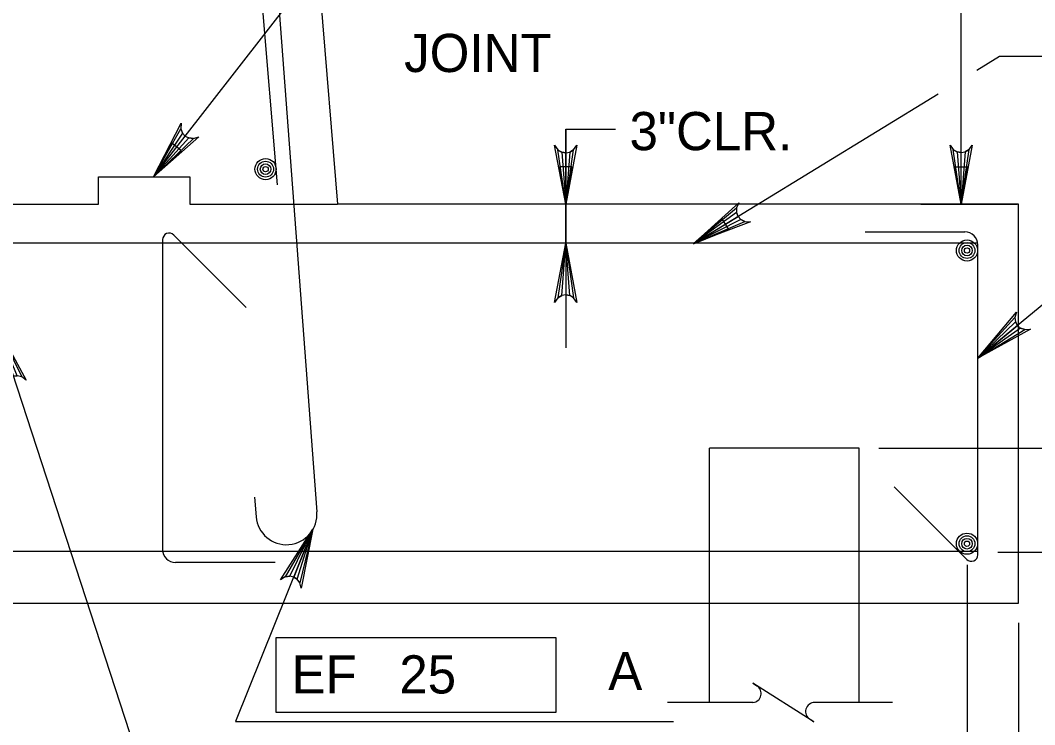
# Model space of a CAD drawing. Extents: x 638340 to 640242, y 295465 to 298435.
# Drawn here: x 639971.8 to 640051.5, y 298208.5 to 298263.9 of the extents above; entities that cross this region are included whole.
import ezdxf

# ---------------------------------------------------------------- set-up
doc = ezdxf.new("R2010")
doc.units = 0
for name, color, linetype in [('Level 3', 7, 'Continuous'), ('Level 4', 7, 'Continuous'), ('Level 5', 7, 'Continuous'), ('Level 6', 7, 'Continuous'), ('Level 7', 7, 'Continuous'), ('Level 8', 7, 'Continuous'), ('Level 9', 7, 'Continuous')]:
    doc.layers.add(name, color=color, linetype=linetype)

msp = doc.modelspace()

# ---------------------------------------------------------------- linework, layer by layer
at = {"layer": 'Level 3'}
for p, q in [((640039.268, 298230.284), (640095.226, 298230.284)), ((640048.611, 298222.099), (640081.55, 298222.099))]:
    msp.add_line(p, q, dxfattribs=at)
at = {"layer": 'Level 4'}
for p, q in [((640045.737, 298249.445), (640045.737, 298311.252)), ((639982.254, 298251.603), (639997.895, 298271.717)), ((640046.971, 298259.984), (640048.764, 298261.081)), ((640048.764, 298261.081), (640084.556, 298261.081)), ((640024.752, 298246.374), (640043.921, 298258.115)), ((640024.752, 298246.374), (640043.921, 298258.115)), ((640014.652, 298255.332), (640014.652, 298238.165)), ((640014.653, 298246.374), (640014.653, 298255.332)), ((640014.653, 298255.332), (640018.566, 298255.332)), ((640042.568, 298249.445), (640050.156, 298249.445)), ((640042.568, 298249.445), (640050.156, 298249.445)), ((640053.121, 298242.35), (640047.051, 298237.338)), ((639969.961, 298239.776), (639984.381, 298195.585)), ((639994.782, 298223.906), (639988.69, 298208.795)), ((640046.201, 298221.101), (640046.201, 298175.428)), ((640050.258, 298216.56), (640050.258, 298158.658)), ((639991.877, 298215.41), (640013.875, 298215.41)), ((639991.877, 298209.515), (639991.877, 298215.41)), ((640013.875, 298215.41), (640013.875, 298209.515)), ((640013.875, 298209.515), (639991.877, 298209.515)), ((639988.69, 298208.795), (640023.134, 298208.795))]:
    msp.add_line(p, q, dxfattribs=at)
for points in [[(639982.254, 298251.603), (639984.421, 298255.81), (639984.398, 298255.375), (639984.529, 298255.038), (639984.743, 298254.803), (639985.022, 298254.656), (639985.381, 298254.61), (639985.797, 298254.739), (639982.254, 298251.603), (639985.381, 298254.61), (639985.022, 298254.656), (639982.254, 298251.603), (639984.743, 298254.803), (639984.529, 298255.038), (639982.254, 298251.603), (639984.398, 298255.375)], [(640014.653, 298249.437), (640013.781, 298254.088), (640014.029, 298253.73), (640014.341, 298253.545), (640014.653, 298253.491), (640014.964, 298253.545), (640015.276, 298253.73), (640015.524, 298254.088), (640014.653, 298249.437), (640015.276, 298253.73), (640014.964, 298253.545), (640014.653, 298249.437), (640014.653, 298253.491), (640014.341, 298253.545), (640014.653, 298249.437), (640014.029, 298253.73)], [(640045.737, 298249.445), (640044.866, 298254.096), (640045.113, 298253.739), (640045.425, 298253.554), (640045.737, 298253.5), (640046.049, 298253.554), (640046.361, 298253.739), (640046.608, 298254.096), (640045.737, 298249.445), (640046.361, 298253.739), (640046.049, 298253.554), (640045.737, 298249.445), (640045.737, 298253.5), (640045.425, 298253.554), (640045.737, 298249.445), (640045.113, 298253.739)], [(640024.752, 298246.374), (640028.264, 298249.547), (640028.087, 298249.148), (640028.092, 298248.786), (640028.21, 298248.49), (640028.418, 298248.253), (640028.738, 298248.085), (640029.175, 298248.06), (640024.752, 298246.374), (640028.738, 298248.085), (640028.418, 298248.253), (640024.752, 298246.374), (640028.21, 298248.49), (640028.092, 298248.786), (640024.752, 298246.374), (640028.087, 298249.148)], [(640024.752, 298246.374), (640028.264, 298249.547), (640028.087, 298249.148), (640028.092, 298248.786), (640028.21, 298248.49), (640028.418, 298248.253), (640028.738, 298248.085), (640029.175, 298248.06), (640024.752, 298246.374), (640028.738, 298248.085), (640028.418, 298248.253), (640024.752, 298246.374), (640028.21, 298248.49), (640028.092, 298248.786), (640024.752, 298246.374), (640028.087, 298249.148)], [(640014.653, 298246.374), (640015.524, 298241.722), (640015.276, 298242.08), (640014.964, 298242.265), (640014.653, 298242.319), (640014.341, 298242.265), (640014.029, 298242.08), (640013.781, 298241.722), (640014.653, 298246.374), (640014.029, 298242.08), (640014.341, 298242.265), (640014.653, 298246.374), (640014.653, 298242.319), (640014.964, 298242.265), (640014.653, 298246.374), (640015.276, 298242.08)], [(640047.051, 298237.339), (640050.083, 298240.971), (640049.964, 298240.553), (640050.02, 298240.194), (640050.179, 298239.919), (640050.418, 298239.713), (640050.759, 298239.591), (640051.193, 298239.628), (640047.051, 298237.339), (640050.759, 298239.591), (640050.418, 298239.713), (640047.051, 298237.339), (640050.179, 298239.919), (640050.02, 298240.194), (640047.051, 298237.339), (640049.964, 298240.553)], [(639969.961, 298239.776), (639972.234, 298235.625), (639971.886, 298235.887), (639971.533, 298235.966), (639971.219, 298235.921), (639970.938, 298235.773), (639970.699, 298235.501), (639970.574, 298235.083), (639969.961, 298239.776), (639970.699, 298235.501), (639970.938, 298235.773), (639969.961, 298239.776), (639971.219, 298235.921), (639971.533, 298235.966), (639969.961, 298239.776), (639971.886, 298235.887)], [(639994.782, 298223.906), (639993.853, 298219.265), (639993.755, 298219.691), (639993.535, 298219.98), (639993.266, 298220.145), (639992.956, 298220.213), (639992.599, 298220.157), (639992.235, 298219.918), (639994.782, 298223.906), (639992.599, 298220.157), (639992.956, 298220.213), (639994.782, 298223.906), (639993.266, 298220.145), (639993.535, 298219.98), (639994.782, 298223.906), (639993.755, 298219.691)]]:
    msp.add_lwpolyline(points, dxfattribs=at)
for points in [[(639984.45, 298253.629), (639983.674, 298254.232), (639982.254, 298251.603)], [(640015.143, 298252.383), (640014.16, 298252.383), (640014.653, 298249.437)], [(640045.244, 298252.391), (640046.228, 298252.391), (640045.737, 298249.445)], [(640027.468, 298247.459), (640026.954, 298248.297), (640024.698, 298246.338)], [(640027.468, 298247.459), (640026.954, 298248.297), (640024.698, 298246.338)]]:
    msp.add_lwpolyline(points, close=True, dxfattribs=at)
at = {"layer": 'Level 5'}
msp.add_line((640046.271, 298249.437), (640046.271, 298249.437), dxfattribs=at)
at = {"layer": 'Level 6'}
for p, q in [((639989.943, 298293.758), (639995.084, 298225.283)), ((639988.426, 298293.505), (639991.969, 298250.979)), ((639982.961, 298246.663), (639982.961, 298222.315)), ((639989.528, 298241.331), (639983.834, 298247.024)), ((640038.189, 298247.268), (640046.028, 298247.268)), ((640047.043, 298246.374), (639939.419, 298246.374)), ((640047.051, 298221.897), (640047.051, 298246.245)), ((640040.485, 298227.229), (640046.178, 298221.536)), ((639990.187, 298226.416), (639990.314, 298224.885)), ((639939.411, 298222.184), (640047.051, 298222.184)), ((639991.823, 298221.29), (639983.984, 298221.29))]:
    msp.add_line(p, q, dxfattribs=at)
for centre, radius in [((639991.056, 298252.2), 0.832), ((639991.056, 298252.2), 0.624), ((639991.056, 298252.2), 0.416), ((639991.056, 298252.2), 0.208), ((640046.201, 298245.807), 0.832), ((640046.201, 298245.807), 0.624), ((640046.201, 298245.807), 0.416), ((640046.201, 298245.807), 0.208), ((640046.2, 298222.768), 0.832), ((640046.2, 298222.768), 0.624), ((640046.2, 298222.768), 0.416), ((640046.2, 298222.768), 0.208)]:
    msp.add_circle(centre, radius, dxfattribs=at)
for centre, radius, start, end in [((639983.471, 298246.663), 0.511, 45, 180), ((640046.027, 298246.245), 1.024, 0, 90), ((639992.699, 298225.085), 2.394, 184.76364, 4.76364), ((639983.983, 298222.315), 1.024, 180, 270), ((640046.539, 298221.898), 0.511, 225, 0)]:
    msp.add_arc(centre, radius, start, end, dxfattribs=at)
at = {"layer": 'Level 7'}
msp.add_lwpolyline([(639966.902, 298249.445), (639977.912, 298249.445), (639977.912, 298251.603), (639985.09, 298251.603), (639985.09, 298249.445), (639996.718, 298249.445)], dxfattribs=at)
at = {"layer": 'Level 8'}
for p, q in [((640037.734, 298230.284), (640025.944, 298230.284)), ((640025.945, 298218.094), (640025.945, 298230.284)), ((640037.734, 298218.009), (640037.734, 298230.284)), ((640025.945, 298210.291), (640025.945, 298218.094)), ((640037.734, 298210.29), (640037.734, 298218.009)), ((640029.377, 298210.29), (640022.656, 298210.29)), ((640040.356, 298210.29), (640034.224, 298210.29))]:
    msp.add_line(p, q, dxfattribs=at)
msp.add_lwpolyline([(640033.868, 298208.968), (640034.167, 298208.781), (640029.366, 298211.8), (640029.686, 298211.596)], dxfattribs=at)
for centre, start, end in [((640029.31, 298210.997), 275.32859, 57.86724), ((640034.222, 298209.582), 90, 240)]:
    msp.add_arc(centre, 0.709, start, end, dxfattribs=at)
at = {"layer": 'Level 9'}
for p, q in [((639985.386, 298385.435), (639996.718, 298249.445)), ((640050.258, 298249.445), (639996.718, 298249.445)), ((640050.258, 298249.445), (639996.718, 298249.445)), ((640050.258, 298218.094), (640050.258, 298249.445)), ((639936.202, 298218.094), (640050.258, 298218.094))]:
    msp.add_line(p, q, dxfattribs=at)

# ---------------------------------------------------------------- texts
at = {"layer": 'Level 3'}
msp.add_text('3"CLR.', height=3.0001, dxfattribs=at).set_placement((640019.67, 298253.691))
at = {"layer": 'Level 4'}
for s, height, p in [('JOINT', 3.0001, (640001.952, 298259.831)), ('EF   25', 3.0001, (639993.102, 298210.999)), ('A', 3, (640017.998, 298211.269))]:
    msp.add_text(s, height=height, dxfattribs=at).set_placement(p)

doc.saveas('drawing.dxf')
